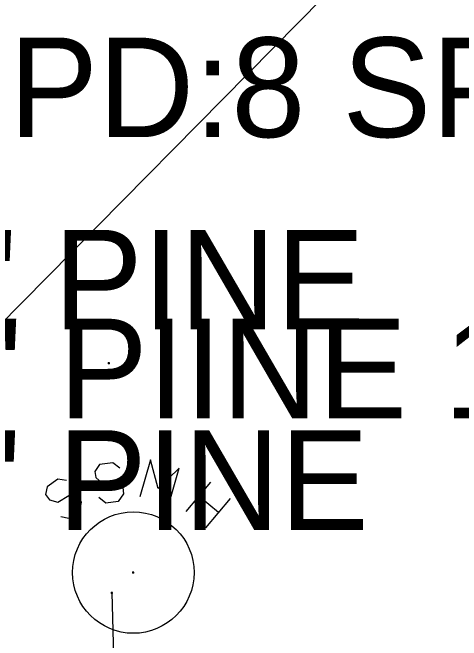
# Model space of a CAD drawing. Extents: x 1930288 to 1941089, y 588389 to 611475.
# Drawn here: x 1930644.44 to 1930666.96, y 598088.44 to 598119.95 of the extents above; entities that cross this region are included whole.
import ezdxf

# ---------------------------------------------------------------- set-up
doc = ezdxf.new("R2010")
doc.units = 0
for name, color, linetype in [('S_GAS_UTILITIES', 7, 'Continuous'), ('S_MSC_PT_SYM', 7, 'Continuous'), ('S_SANITARY_SEWER', 7, 'Continuous'), ('S_SECONDARY_CTL_ANNOT', 7, 'Continuous'), ('S_TREE_ANNOT', 7, 'Continuous'), ('S_UTL_PT_SYM', 7, 'Continuous')]:
    doc.layers.add(name, color=color, linetype=linetype)

msp = doc.modelspace()

# ---------------------------------------------------------------- linework, layer by layer
at = {"layer": 'S_GAS_UTILITIES'}
msp.add_line((1930683.075, 598144.05), (1930639.467, 598099.886), dxfattribs=at)
at = {"layer": 'S_MSC_PT_SYM'}
for points in [[(1930649.264, 598102.354), (1930649.264, 598102.404), (1930649.264, 598102.354), (1930649.214, 598102.354), (1930649.264, 598102.354), (1930649.264, 598102.304), (1930649.264, 598102.354), (1930649.314, 598102.354)], [(1930649.427, 598090.83), (1930649.427, 598090.88), (1930649.427, 598090.83), (1930649.377, 598090.83), (1930649.427, 598090.83), (1930649.427, 598090.78), (1930649.427, 598090.83), (1930649.477, 598090.83)]]:
    msp.add_lwpolyline(points, dxfattribs=at)
at = {"layer": 'S_SANITARY_SEWER'}
for p, q in [((1930646.715, 598096.532), (1930646.172, 598096.145)), ((1930647.141, 598096.455), (1930646.715, 598096.532)), ((1930653.147, 598094.905), (1930654.387, 598096.377)), ((1930646.172, 598096.145), (1930646.095, 598095.757)), ((1930646.095, 598095.757), (1930646.289, 598095.486)), ((1930646.715, 598095.37), (1930647.257, 598095.718)), ((1930647.257, 598095.718), (1930647.722, 598095.641)), ((1930653.806, 598095.68), (1930654.775, 598094.866)), ((1930646.289, 598095.486), (1930646.715, 598095.37)), ((1930647.722, 598095.641), (1930647.877, 598095.37)), ((1930647.877, 598095.37), (1930647.8, 598094.943)), ((1930655.356, 598095.563), (1930654.116, 598094.091)), ((1930647.8, 598094.943), (1930647.257, 598094.556)), ((1930647.257, 598094.556), (1930646.87, 598094.633)), ((1930649.427, 598090.83), (1930658.173, 597764.229))]:
    msp.add_line(p, q, dxfattribs=at)
for points in [[(1930649.815, 598097.075), (1930649.466, 598097.346), (1930648.807, 598097.268), (1930648.575, 598096.92), (1930648.614, 598096.61), (1930648.962, 598096.3), (1930649.582, 598096.416), (1930649.97, 598096.106), (1930650.009, 598095.796), (1930649.737, 598095.408), (1930649.117, 598095.331), (1930648.769, 598095.602)], [(1930652.256, 598095.215), (1930652.799, 598097.075), (1930651.752, 598096.067), (1930651.365, 598097.501), (1930650.822, 598095.641)]]:
    msp.add_lwpolyline(points, dxfattribs=at)
msp.add_circle((1930650.499, 598091.841), 3.048, dxfattribs=at)
at = {"layer": 'S_UTL_PT_SYM'}
for points in [[(1930650.499, 598091.841), (1930650.499, 598091.891), (1930650.499, 598091.841), (1930650.449, 598091.841), (1930650.499, 598091.841), (1930650.499, 598091.791), (1930650.499, 598091.841), (1930650.549, 598091.841)], [(1930649.427, 598090.83), (1930649.427, 598090.88), (1930649.427, 598090.83), (1930649.377, 598090.83), (1930649.427, 598090.83), (1930649.427, 598090.78), (1930649.427, 598090.83), (1930649.477, 598090.83)]]:
    msp.add_lwpolyline(points, dxfattribs=at)

# ---------------------------------------------------------------- texts
at = {"layer": 'S_SECONDARY_CTL_ANNOT'}
msp.add_text('PD:8 SPIKE', height=5, dxfattribs=at).set_placement((1930644.268, 598113.696))
at = {"layer": 'S_TREE_ANNOT'}
for s, p in [('16" PINE', (1930634.84, 598104.043)), ('18" PIINE 18" PINE', (1930635.096, 598099.582)), ('18" PINE', (1930635.044, 598093.985))]:
    msp.add_text(s, height=5, dxfattribs=at).set_placement(p)

doc.saveas('drawing.dxf')
